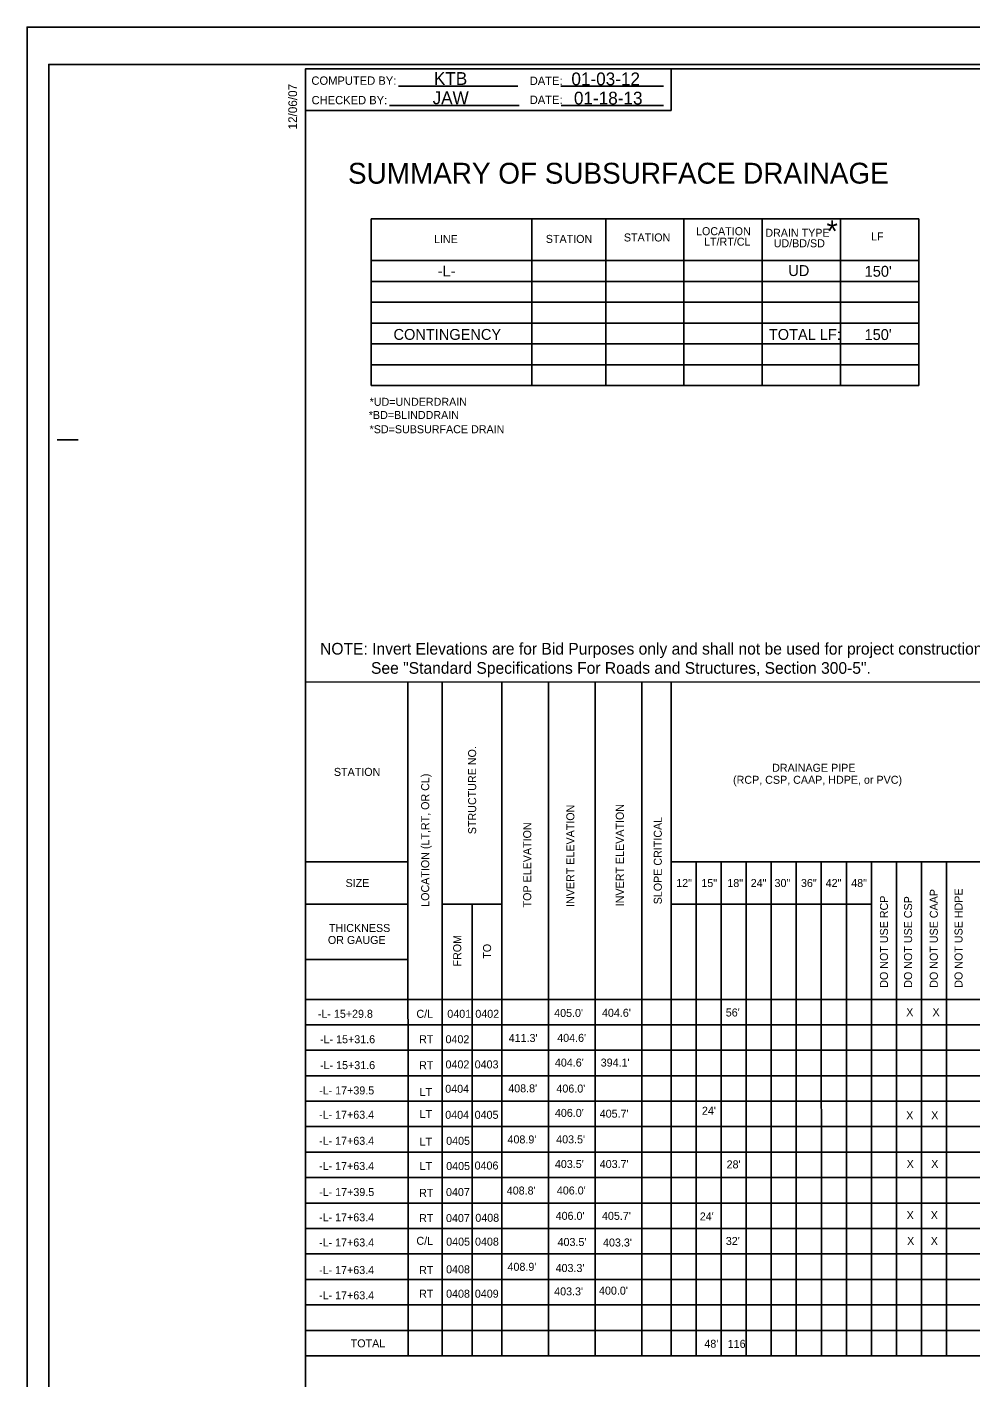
# Model space of a CAD drawing. Extents: x 573359 to 575895, y -54193 to -50493.
# Drawn here: x 573602 to 574168, y -51303 to -50493 of the extents above; entities that cross this region are included whole.
import ezdxf

# ---------------------------------------------------------------- set-up
doc = ezdxf.new("R2010")
doc.units = 0
for name, color, linetype in [('Prop Dimension Text', 7, 'Continuous'), ('Sheet Cutting Line CELL', 7, 'Continuous'), ('Sheet Pipe Summary CELL', 7, 'Continuous'), ('Sheet Pipe Summary Grid CELL', 7, 'Continuous'), ('Sheet Plot Border Inside CELL', 7, 'Continuous'), ('Sheet Plot Border Outside CELL', 7, 'Continuous'), ('Sheet Summary Combination CELL', 7, 'Continuous'), ('Sheet Summary Combination Grid CELL', 7, 'Continuous')]:
    doc.layers.add(name, color=color, linetype=linetype)

msp = doc.modelspace()

# ---------------------------------------------------------------- linework, layer by layer
at = {"layer": 'Sheet Cutting Line CELL'}
for p, q in [((575286.01, -50493.3), (573602.01, -50493.3)), ((573602.01, -50493.3), (573602.01, -51593.3))]:
    msp.add_line(p, q, dxfattribs=at)
at = {"layer": 'Sheet Pipe Summary Grid CELL'}
for p, q in [((575269.01, -50886), (573769.01, -50886.1)), ((573830.36, -51290.2), (573830.34, -50886.1)), ((573850.91, -51290.2), (573850.89, -50886.1)), ((573886.66, -51290.2), (573886.64, -50886.1)), ((573914.63, -51290.2), (573914.61, -50886.1)), ((573942.61, -51290.2), (573942.59, -50886.1)), ((573970.58, -51290.2), (573970.56, -50886.1)), ((573988.08, -51290.2), (573988.06, -50886.1)), ((573830.34, -50993.95), (573769.01, -50993.95)), ((574505.57, -50993.87), (573988.07, -50993.95)), ((574003.08, -51290.2), (574003.07, -50993.94)), ((574018.08, -51290.2), (574018.07, -50993.94)), ((574033.08, -51290.2), (574033.07, -50993.94)), ((574048.08, -51290.2), (574048.07, -50993.94)), ((574063.08, -51290.2), (574063.07, -50993.94)), ((574078.08, -51290.2), (574078.07, -50993.94)), ((574093.08, -51290.2), (574093.07, -50993.94)), ((574108.08, -51290.2), (574108.07, -50993.94)), ((574123.08, -51290.2), (574123.07, -50993.94)), ((574138.08, -51290.2), (574138.07, -50993.94)), ((574153.08, -51290.2), (574153.07, -50993.94)), ((573830.34, -51019.35), (573769.01, -51019.35)), ((573886.65, -51019.35), (573850.9, -51019.35)), ((573868.8, -51290.2), (573868.79, -51019.35)), ((574108.07, -51019.32), (573988.07, -51019.33)), ((573830.34, -51052.5), (573769.01, -51052.5)), ((575269.01, -51076.4), (573769.01, -51076.4)), ((575269.01, -51091.7), (573769.01, -51091.7)), ((575269.01, -51106.95), (573769.01, -51106.95)), ((575269.01, -51122.2), (573769.01, -51122.2)), ((575269.01, -51137.5), (573769.01, -51137.5)), ((575269.01, -51152.75), (573769.01, -51152.75)), ((575269.01, -51168.05), (573769.01, -51168.05)), ((575269.01, -51183.3), (573769.01, -51183.3)), ((575269.01, -51198.55), (573769.01, -51198.55)), ((575269.01, -51213.85), (573769.01, -51213.85)), ((575269.01, -51213.85), (573769.01, -51213.85)), ((575269.01, -51229.1), (573769.01, -51229.1)), ((575269.01, -51244.4), (573769.01, -51244.4)), ((575269.01, -51259.65), (573769.01, -51259.65)), ((575269.01, -51274.9), (573769.01, -51274.9)), ((575269.01, -51274.9), (573769.01, -51274.9)), ((575269.01, -51290.2), (573769.01, -51290.2)), ((575269.01, -51290.2), (573769.01, -51290.2))]:
    msp.add_line(p, q, dxfattribs=at)
at = {"layer": 'Sheet Plot Border Inside CELL'}
msp.add_lwpolyline([(575281.51, -50515.75), (573615.01, -50515.75), (573615.01, -51570.85), (575281.51, -51570.85)], close=True, dxfattribs=at)
at = {"layer": 'Sheet Plot Border Outside CELL'}
msp.add_lwpolyline([(575286.01, -50493.3), (573602.01, -50493.3), (573602.01, -51593.3), (575286.01, -51593.3)], close=True, dxfattribs=at)
at = {"layer": 'Sheet Summary Combination CELL'}
for p, q in [((573824.66, -50528.7), (573896.21, -50528.7)), ((573922.01, -50528.85), (573983.41, -50528.85)), ((573819.21, -50540.4), (573896.91, -50540.4)), ((573922.16, -50540.35), (573983.56, -50540.35)), ((573902.52, -50608.4), (573902.52, -50608.4)), ((573908.77, -50608.5), (573908.77, -50608.5)), ((573917.82, -50608.3), (573917.82, -50608.3)), ((573923.42, -50608.4), (573923.42, -50608.4)), ((573620.11, -50740.8), (573632.61, -50740.8))]:
    msp.add_line(p, q, dxfattribs=at)
for points in [[(575269.01, -50518.3), (573769.01, -50518.3), (573769.01, -51568.3), (575269.01, -51568.3)], [(573769.01, -50518.3), (573988.01, -50518.3), (573988.01, -50543.3), (573769.01, -50543.3)]]:
    msp.add_lwpolyline(points, close=True, dxfattribs=at)
at = {"layer": 'Sheet Summary Combination Grid CELL'}
for p, q in [((573808.17, -50608.35), (574136.42, -50608.35)), ((573808.17, -50608.35), (573808.17, -50708.35)), ((573904.51, -50608.35), (573904.51, -50708.35)), ((573948.82, -50608.35), (573948.82, -50708.35)), ((573995.72, -50608.35), (573995.72, -50708.35)), ((574042.62, -50608.35), (574042.62, -50708.35)), ((574089.52, -50608.35), (574089.52, -50708.35)), ((574136.42, -50608.35), (574136.42, -50708.35)), ((573808.17, -50633.35), (574136.42, -50633.35)), ((573808.17, -50645.85), (574136.42, -50645.85)), ((573808.17, -50658.35), (574136.42, -50658.35)), ((573808.17, -50670.85), (574136.42, -50670.85)), ((573808.17, -50683.35), (574136.42, -50683.35)), ((573808.17, -50695.85), (574136.42, -50695.85)), ((573808.17, -50708.35), (574136.42, -50708.35))]:
    msp.add_line(p, q, dxfattribs=at)

# ---------------------------------------------------------------- texts
at = {"layer": 'Prop Dimension Text'}
for s, height, p in [('KTB', 7.68, (573845.88, -50528.03)), ('01-03-12', 7.68, (573928.28, -50528.25)), ('JAW', 7.68, (573845.08, -50539.59)), ('01-18-13', 7.68, (573929.8, -50539.76)), ('*', 13.06, (574081.17, -50622.23)), ('-L-', 6.528, (573848.15, -50642.85)), ('UD', 6.528, (574058.28, -50642.63)), ("150'", 6.528, (574104.06, -50643.06)), ('CONTINGENCY', 6.528, (573821.66, -50680.92)), ('TOTAL LF:', 6.528, (574046.62, -50680.92)), ("150'", 6.528, (574103.98, -50681.02)), ('-L- 15+29.8', 4.8, (573776.3, -51087.48)), ('C/L', 4.8, (573835.4, -51087.48)), ('0401', 4.8, (573853.9, -51087.48)), ('0402', 4.8, (573870.7, -51087.48)), ("405.0'", 4.8, (573917.96, -51086.97)), ("404.6'", 4.8, (573946.61, -51086.88)), ("56'", 4.8, (574020.81, -51086.69)), ('X', 4.8, (574128.96, -51086.52)), ('X', 4.8, (574144.71, -51086.52)), ("411.3'", 4.8, (573890.7, -51101.98)), ("404.6'", 4.8, (573919.79, -51101.9)), ('-L- 15+31.6', 4.8, (573777.63, -51102.74)), ('RT', 4.8, (573837.02, -51102.74)), ('0402', 4.8, (573852.83, -51102.74)), ('-L- 15+31.6', 4.8, (573777.63, -51118.26)), ('RT', 4.8, (573837.02, -51118.3)), ('0402', 4.8, (573852.83, -51117.82)), ('0403', 4.8, (573870.32, -51117.82)), ("404.6'", 4.8, (573918.4, -51116.72)), ("394.1'", 4.8, (573945.85, -51116.72)), ('-L- 17+39.5', 4.8, (573777.08, -51133.42)), ('LT', 4.8, (573837.31, -51134.39)), ('0404', 4.8, (573852.67, -51132.44)), ("408.8'", 4.8, (573890.44, -51132.18)), ("406.0'", 4.8, (573919.31, -51132.31)), ('-L- 17+63.4', 4.8, (573777.04, -51148.01)), ('LT', 4.8, (573837.31, -51147.56)), ('0404', 4.8, (573852.67, -51148.05)), ('0405', 4.8, (573870.29, -51148.05)), ("406.0'", 4.8, (573918.4, -51146.92)), ("405.7'", 4.8, (573945.27, -51147.36)), ("24'", 4.8, (574006.52, -51145.61)), ('X', 4.8, (574128.96, -51148.35)), ('X', 4.8, (574143.93, -51148.35)), ('-L- 17+63.4', 4.8, (573777.04, -51163.65)), ('LT', 4.8, (573837.31, -51164.14)), ('0405', 4.8, (573853.22, -51163.65)), ("408.9'", 4.8, (573889.99, -51162.82)), ("403.5'", 4.8, (573919.17, -51162.77)), ('-L- 17+63.4', 4.8, (573777.04, -51178.77)), ('LT', 4.8, (573837.31, -51178.77)), ('0405', 4.8, (573853.22, -51178.77)), ('0406', 4.8, (573870.26, -51178.47)), ("403.5'", 4.8, (573918.4, -51177.56)), ("403.7'", 4.8, (573945.27, -51177.56)), ("28'", 4.8, (574021.31, -51177.79)), ('X', 4.8, (574129.23, -51177.49)), ('X', 4.8, (574143.93, -51177.49)), ('-L- 17+39.5', 4.8, (573777.08, -51194.37)), ('RT', 4.8, (573837.02, -51194.86)), ('0407', 4.8, (573853.13, -51194.37)), ("408.8'", 4.8, (573889.55, -51193.46)), ("406.0'", 4.8, (573919.57, -51193.43)), ('-L- 17+63.4', 4.8, (573777.04, -51209.53)), ('RT', 4.8, (573837.02, -51209.98)), ('0407', 4.8, (573853.13, -51209.98)), ('0408', 4.8, (573870.69, -51209.8)), ("406.0'", 4.8, (573918.85, -51208.64)), ("405.7'", 4.8, (573946.61, -51208.64)), ("24'", 4.8, (574005.22, -51209)), ('X', 4.8, (574129.23, -51208.21)), ('X', 4.8, (574143.66, -51208.21)), ('C/L', 4.8, (573835.4, -51223.63)), ("32'", 4.8, (574020.83, -51223.7)), ('X', 4.8, (574129.49, -51223.7)), ('X', 4.8, (574143.66, -51223.7)), ('-L- 17+63.4', 4.8, (573777.04, -51224.61)), ('0405', 4.8, (573853.22, -51224.12)), ('0408', 4.8, (573870.52, -51224.09)), ("403.5'", 4.8, (573920, -51224.34)), ("403.3'", 4.8, (573947.24, -51224.63)), ("408.9'", 4.8, (573889.99, -51239.2)), ("403.3'", 4.8, (573918.81, -51239.93)), ('-L- 17+63.4', 4.8, (573777.04, -51241.15)), ('RT', 4.8, (573837.02, -51241.19)), ('0408', 4.8, (573853.19, -51240.7)), ('-L- 17+63.4', 4.8, (573777.04, -51256.3)), ('RT', 4.8, (573837.02, -51255.33)), ('0408', 4.8, (573853.19, -51255.33)), ('0409', 4.8, (573870.42, -51255.32)), ("403.3'", 4.8, (573917.96, -51253.94)), ("400.0'", 4.8, (573944.83, -51253.49)), ('TOTAL', 4.8, (573796, -51285.09)), ("48'", 4.8, (574007.98, -51285.33)), ("116'", 4.8, (574021.97, -51285.4))]:
    msp.add_text(s, height=height, dxfattribs=at).set_placement(p)
at = {"layer": 'Sheet Pipe Summary CELL'}
for s, height, p in [('NOTE: Invert Elevations are for Bid Purposes only and shall not be used for project construction stakeout.', 7, (573777.65, -50869.64)), ('See "Standard Specifications For Roads and Structures, Section 300-5".', 7, (573808.18, -50881.17)), ('DRAINAGE PIPE', 4.8, (574048.59, -50939.94)), ('(RCP, CSP, CAAP, HDPE, or PVC)', 4.8, (574025.17, -50947.14)), ('SIZE', 4.8, (573792.94, -51009.05)), ('12"', 4.8, (573991.11, -51009.04)), ('15"', 4.8, (574006.18, -51009.04)), ('18"', 4.8, (574021.76, -51009.04)), ('24"', 4.8, (574035.74, -51009.04)), ('30"', 4.8, (574050.04, -51009.04)), ('36"', 4.8, (574065.87, -51009.04)), ('42"', 4.8, (574080.68, -51009.04)), ('48"', 4.8, (574096, -51009.04)), ('THICKNESS', 4.8, (573782.99, -51036)), ('OR GAUGE', 4.8, (573782.34, -51043.2))]:
    msp.add_text(s, height=height, dxfattribs=at).set_placement(p)
for s, rotation, p in [('STRUCTURE NO.', 90, (573871.19, -50977.35)), ('STATION', 360, (573785.94, -50942.4)), ('LOCATION (LT,RT, OR CL)', 90, (573843.04, -51020.9)), ('INVERT ELEVATION', 90, (573959.71, -51020.6)), ('INVERT ELEVATION', 90, (573930.05, -51021)), ('SLOPE CRITICAL', 90, (573982.46, -51019.4)), ('TOP ELEVATION', 90, (573904.19, -51021.28)), ('DO NOT USE RCP', 90, (574118.01, -51069.46)), ('DO NOT USE CSP', 90, (574132.47, -51069.46)), ('DO NOT USE CAAP', 90, (574147.89, -51069.46)), ('DO NOT USE HDPE', 90, (574162.7, -51069.46)), ('FROM', 90, (573862.24, -51056.7)), ('TO', 90, (573880.14, -51052.05))]:
    msp.add_text(s, height=4.8, rotation=rotation, dxfattribs=at).set_placement(p)
at = {"layer": 'Sheet Summary Combination CELL'}
for s, height, rotation, p in [('12/06/07', 5.25, 90, (573763.86, -50554.74)), ('SUMMARY OF SUBSURFACE DRAINAGE', 12.5001, 0.01193, (573794.38, -50587.26))]:
    msp.add_text(s, height=height, rotation=rotation, dxfattribs=at).set_placement(p)
for s, height, p in [('COMPUTED BY:', 4.9998, (573772.46, -50527.95)), ('DATE:', 5, (573903.31, -50528.05)), ('CHECKED BY:', 4.9998, (573772.56, -50539.65)), ('DATE:', 5, (573903.31, -50539.45)), ('LINE', 4.8, (573845.92, -50622.91)), ('STATION', 4.8, (573912.95, -50622.77)), ('STATION', 4.8, (573959.74, -50621.9)), ('*UD=UNDERDRAIN', 4.8, (573807.37, -50720.47)), ('*BD=BLINDDRAIN', 4.8, (573806.84, -50728.37)), ('*SD=SUBSURFACE DRAIN', 4.8, (573807.32, -50736.91))]:
    msp.add_text(s, height=height, dxfattribs=at).set_placement(p)
at = {"layer": 'Sheet Summary Combination Grid CELL'}
for s, p in [('LOCATION', (574002.97, -50618.14)), ('LT/RT/CL', (574007.8, -50624.44)), ('DRAIN TYPE', (574044.51, -50619.1)), ('LF', (574107.88, -50621.29)), ('UD/BD/SD', (574049.53, -50625.39))]:
    msp.add_text(s, height=4.8, dxfattribs=at).set_placement(p)

doc.saveas('drawing.dxf')
